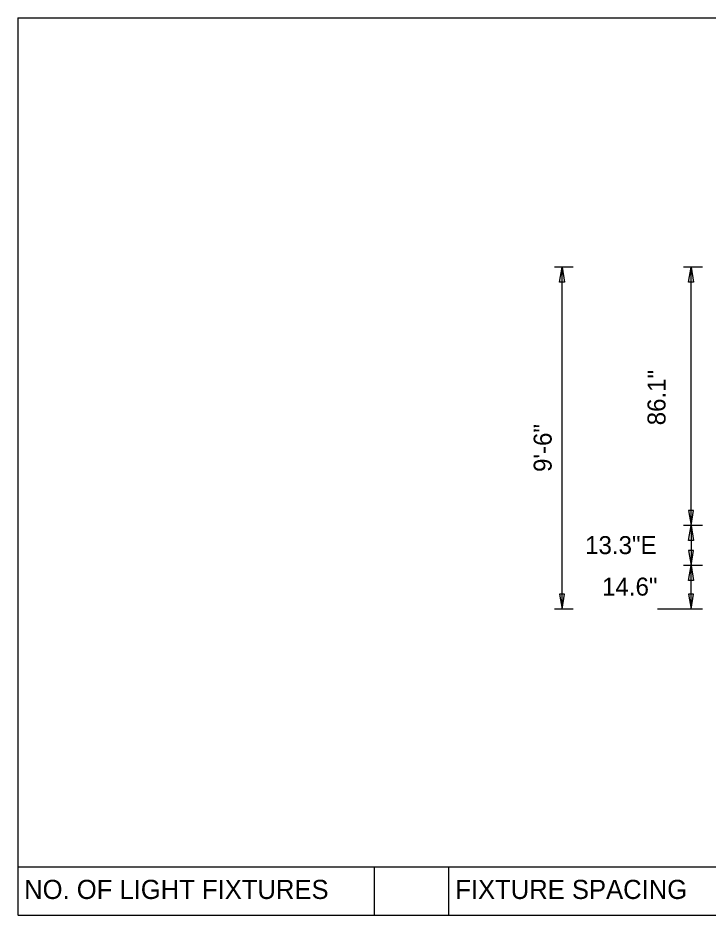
# Model space of a CAD drawing. Extents: x 122633 to 124574, y -23288 to -22025.
# Drawn here: x 122983.5 to 123213.4, y -22906.6 to -22607.5 of the extents above; entities that cross this region are included whole.
import ezdxf

# ---------------------------------------------------------------- set-up
doc = ezdxf.new("R2010")
doc.units = 0
for name, color, linetype in [('GSDims', 7, 'Continuous'), ('SheetLinesMisc2_dp', 7, 'Continuous'), ('TextMinor', 7, 'Continuous')]:
    doc.layers.add(name, color=color, linetype=linetype)

msp = doc.modelspace()

# ---------------------------------------------------------------- linework, layer by layer
at = {"layer": 'GSDims'}
for p, q in [((123168.48, -22690.63), (123162.23, -22690.63)), ((123164.73, -22804.63), (123164.73, -22690.63)), ((123211.49, -22690.63), (123205.24, -22690.63)), ((123207.74, -22776.73), (123207.74, -22690.63)), ((123211.49, -22776.73), (123205.24, -22776.73)), ((123211.49, -22776.73), (123205.24, -22776.73)), ((123207.74, -22776.73), (123207.74, -22790.03)), ((123211.49, -22790.03), (123205.24, -22790.03)), ((123211.49, -22790.03), (123205.24, -22790.03)), ((123207.74, -22804.63), (123207.74, -22790.03)), ((123168.48, -22804.63), (123162.23, -22804.63)), ((123211.49, -22804.63), (123196.49, -22804.63)), ((123211.49, -22804.63), (123205.24, -22804.63))]:
    msp.add_line(p, q, dxfattribs=at)
for points in [[(123164.73, -22690.63), (123165.56, -22695.63), (123163.89, -22695.63)], [(123207.74, -22690.63), (123208.57, -22695.63), (123206.9, -22695.63)], [(123207.74, -22776.73), (123208.57, -22771.73), (123206.9, -22771.73)], [(123207.74, -22776.73), (123208.57, -22781.73), (123206.9, -22781.73)], [(123207.74, -22790.03), (123208.57, -22785.03), (123206.9, -22785.03)], [(123207.74, -22790.03), (123208.57, -22795.03), (123206.9, -22795.03)], [(123164.73, -22804.63), (123165.56, -22799.63), (123163.89, -22799.63)], [(123207.74, -22804.63), (123208.57, -22799.63), (123206.9, -22799.63)]]:
    msp.add_lwpolyline(points, close=True, dxfattribs=at)
at = {"layer": 'SheetLinesMisc2_dp'}
for p, q in [((122983.52, -22607.55), (123597.5, -22607.55)), ((122983.52, -22607.55), (122983.52, -22906.19)), ((122983.52, -22890.59), (123597.5, -22890.59)), ((123102.11, -22890.59), (123102.11, -22906.61)), ((123126.96, -22890.59), (123126.96, -22906.61)), ((122983.52, -22906.19), (122983.52, -22906.59)), ((122983.52, -22906.61), (123597.5, -22906.61))]:
    msp.add_line(p, q, dxfattribs=at)

# ---------------------------------------------------------------- texts
at = {"layer": 'GSDims'}
for s, p in [('86.1"', (123199.2, -22743.34)), ('9\'-6"', (123161.28, -22758.9))]:
    msp.add_text(s, height=6, rotation=90, dxfattribs=at).set_placement(p)
for s, p in [('13.3"E', (123172.42, -22786.29)), ('14.6"', (123178.06, -22800.12))]:
    msp.add_text(s, height=6, dxfattribs=at).set_placement(p)
at = {"layer": 'TextMinor'}
for s, p in [('NO. OF LIGHT FIXTURES', (122985.58, -22901.25)), ('FIXTURE SPACING', (123129.17, -22901.25))]:
    msp.add_text(s, height=6.3774, dxfattribs=at).set_placement(p)

doc.saveas('drawing.dxf')
